// Mitsubishi GX Works2 project: 3U脉冲测试   PLC: FX3U/FX3UC

PROGRAM MAIN
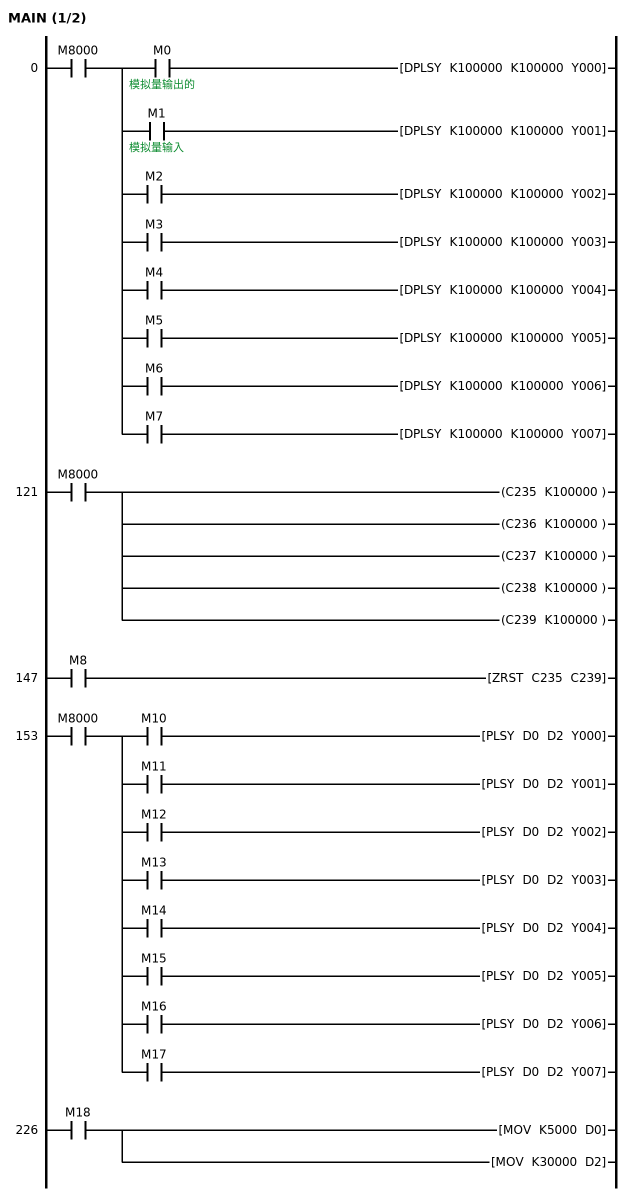
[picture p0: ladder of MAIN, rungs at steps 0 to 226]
0     LD      M8000
      MPS
      AND     M0  ; 模拟量输出的
      DPLSY   K100000 K100000 Y000
      MRD
      AND     M1  ; 模拟量输入
      DPLSY   K100000 K100000 Y001
      MRD
      AND     M2
      DPLSY   K100000 K100000 Y002
      MRD
      AND     M3
      DPLSY   K100000 K100000 Y003
      MRD
      AND     M4
      DPLSY   K100000 K100000 Y004
      MRD
      AND     M5
      DPLSY   K100000 K100000 Y005
      MRD
      AND     M6
      DPLSY   K100000 K100000 Y006
      MPP
      AND     M7
      DPLSY   K100000 K100000 Y007
121   LD      M8000
      OUT     C235 K100000
      OUT     C236 K100000
      OUT     C237 K100000
      OUT     C238 K100000
      OUT     C239 K100000
147   LD      M8
      ZRST    C235 C239
153   LD      M8000
      MPS
      AND     M10
      PLSY    D0 D2 Y000
      MRD
      AND     M11
      PLSY    D0 D2 Y001
      MRD
      AND     M12
      PLSY    D0 D2 Y002
      MRD
      AND     M13
      PLSY    D0 D2 Y003
      MRD
      AND     M14
      PLSY    D0 D2 Y004
      MRD
      AND     M15
      PLSY    D0 D2 Y005
      MRD
      AND     M16
      PLSY    D0 D2 Y006
      MPP
      AND     M17
      PLSY    D0 D2 Y007
226   LD      M18
      MOV     K5000 D0
      MOV     K30000 D2
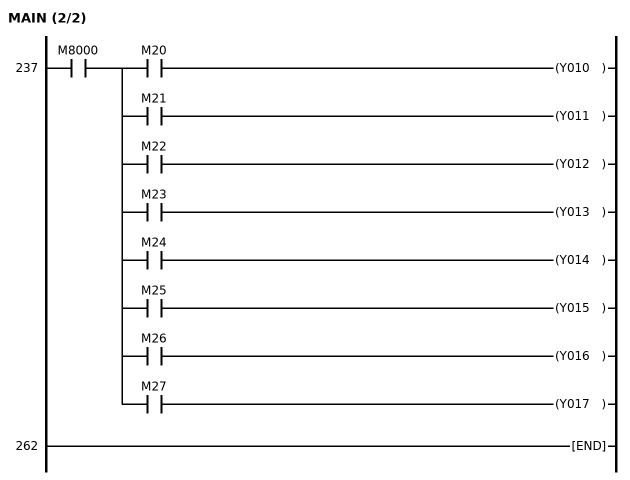
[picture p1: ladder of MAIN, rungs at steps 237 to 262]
237   LD      M8000
      MPS
      AND     M20
      OUT     Y010
      MRD
      AND     M21
      OUT     Y011
      MRD
      AND     M22
      OUT     Y012
      MRD
      AND     M23
      OUT     Y013
      MRD
      AND     M24
      OUT     Y014
      MRD
      AND     M25
      OUT     Y015
      MRD
      AND     M26
      OUT     Y016
      MPP
      AND     M27
      OUT     Y017
262   END
END_PROGRAM

// device comments not shown above
D10  ; 模拟量输出值的地址
D30  ; 模拟量输入地址
D50  ; 热电偶的类型
